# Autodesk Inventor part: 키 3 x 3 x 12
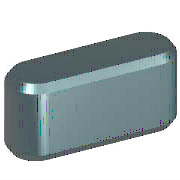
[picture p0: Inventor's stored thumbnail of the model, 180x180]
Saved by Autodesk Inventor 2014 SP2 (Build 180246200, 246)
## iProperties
Created: 2012-02
Part Number: 키 3 x 3 x 12
Material: 강철, 연강
Description: 키 및 해당 키홈
Document SubType Name: Modeling
Standard: KS B 1311
Designer: mduedu
Standards Organization: KS
Language: ko-KR
Size Designation: 3 x 3 x 12
Categories: <MemberInstance><Categories><Category DisplayName="샤프트 부품" InternalName="7f7aeb1f-a693-4053-b835-cee3144e0d98" Mnemonic="SHFT"><Category DisplayName="키" Interna
Density: 7.86 g/cm^3
Appearance: 강철
Mass: 0.790122 g
Surface Area: 1.42216 cm^2
Volume: 0.100524 cm^3
IsCustomPart: 1
Author: mduedu
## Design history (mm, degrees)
workplane "Work Plane1"
workplane "Work Plane2"
sketch "스케치1"
  geometry: L1 (1.5, 1.5)-(10.5, 1.5); L2 (10.5, -1.5)-(1.5, -1.5); L3 (0, 9.4)-(0, -7.4) reference; L4 (-5, 0)-(30, 0) reference; L5 (12, 0)-(12, 7); A1 r 1.5 centre (1.5, 0) between (1.5, 1.5) and (1.5, -1.5); A2 r 1.5 centre (10.5, 0) between (10.5, -1.5) and (10.5, 1.5)
  constraints: 6 end point, 5 point on circle, 4 tangent, 3 point on line, 2 centre point, 1 horizontal, 1 parallel, 1 perpendicular
  dimensions: "d0" = 1.5 radius of A1 (= 0.5 x PB); "d13" = 1.5 radius of A2 (= 0.5 x PB); "d14" = 12 distance between parallel lines of L5 L3 (= NLG)
extrude "본체1" new body sketch "스케치1" taper "d3" = 0 deg; stored distance "d4" = 10
workplane "Work Plane3"
body "Solid1"
chamfer "모따기1" distance "d8" = 0.25 (= PHH); stored, may be unused: second distance "d9" = 0.25 (= PHH), angle "d15" = 45 deg
other parameters: "d1" = -1.8 (= -PNT), "d2" = 1.2 (= PH - PNT), "NLG" = 12 [user parameter; used in 3 equation terms], "PB" = 3 [user parameter; used in 2 equation terms], "PNT" = 1.8 [user parameter; used in 2 equation terms], "PH" = 3 [user parameter; used in 1 equation term], "PHH" = 0.25 [user parameter; used in 2 equation terms], "d10" = 0, "d16" = 0, "d17" = 0, "d18" = 0, "WDMIN" = 8 [user parameter], "PLB2" = 12 (= NLG) [user parameter], "PLB1" = 12 (= NLG) [user parameter], "RR" = 0.08 [user parameter], "PUEB" = 1.4 [user parameter]
